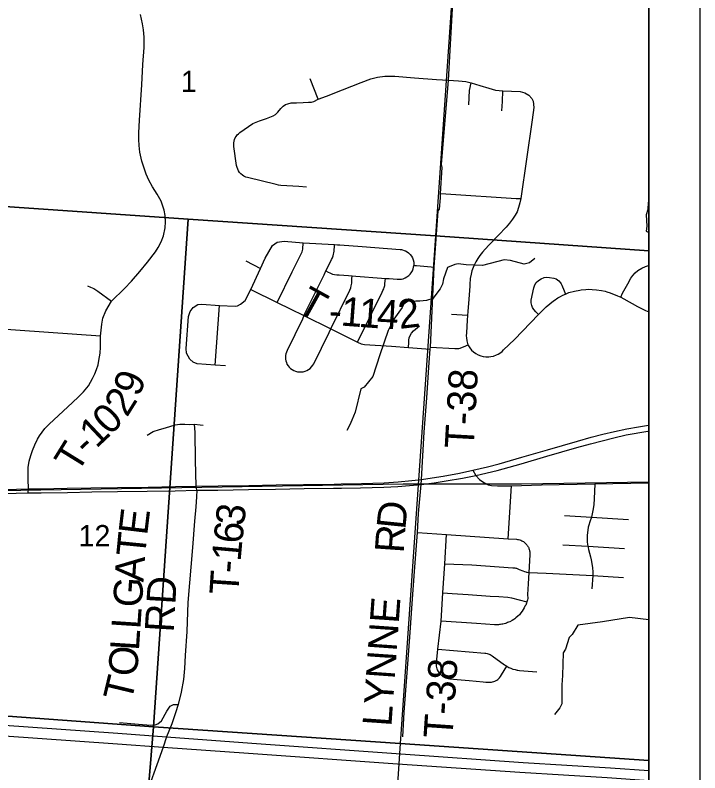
# Model space of a CAD drawing. Extents: x 0 to 34, y 0 to 22.
# Drawn here: x 7.657 to 9, y 18.88 to 20.367 of the extents above; entities that cross this region are included whole.
import ezdxf

# ---------------------------------------------------------------- set-up
doc = ezdxf.new("R2010")
doc.units = 0
for name, color, linetype in [('GM_X_Corporation', 7, 'Continuous'), ('GM_X_Interstate_Route', 7, 'Continuous'), ('GM_X_Minor_River', 7, 'Continuous'), ('GM_X_Rail_Line', 7, 'Continuous'), ('GM_X_Section_Text', 7, 'Continuous'), ('GM_X_Township_Road', 7, 'Continuous'), ('GM_X_Township_Road_Text', 7, 'Continuous'), ('GM_X_US_Route', 7, 'Continuous'), ('SH_Data', 7, 'Continuous')]:
    doc.layers.add(name, color=color, linetype=linetype)

msp = doc.modelspace()

# ---------------------------------------------------------------- linework, layer by layer
at = {"layer": 'GM_X_Corporation'}
for points in [[(6.0904, 18.0983), (6.5673, 18.064), (7.2487, 18.0119), (7.5344, 17.9901), (7.8447, 17.9665), (8.1742, 17.9461), (8.3494, 17.9349), (8.9, 17.9001), (8.9, 20.9), (4.3068, 20.9)], [(6.0906, 18.0978), (6.5646, 18.0583), (7.2489, 18.0114), (7.5346, 17.9896), (7.8449, 17.9659), (8.1744, 17.9455), (8.3496, 17.9344), (8.9, 17.8995), (8.9, 20.9), (4.3071, 20.9)], [(6.0904, 18.0983), (6.5673, 18.064), (7.2487, 18.0119), (7.5344, 17.9901), (7.8447, 17.9665), (8.1742, 17.9461), (8.3494, 17.9349), (8.9, 17.9001), (8.9, 20.4724), (8.5224, 20.4984), (8.4655, 20.5021), (7.8827, 20.5405), (6.676, 20.6183), (5.8237, 20.6711)]]:
    msp.add_lwpolyline(points, dxfattribs=at)
for points in [[(7.5154, 20.5644), (7.7109, 20.5519), (7.7144, 20.5517), (8.2347, 20.5164), (8.5204, 20.4957), (8.4813, 19.9336), (7.9967, 19.9667), (7.4756, 20.0027)], [(8.9, 19.9045), (8.9, 20.4692), (8.881, 20.4706), (8.6271, 20.4885), (8.5204, 20.4957), (8.4813, 19.9336)], [(7.4756, 20.0027), (7.9967, 19.9667), (7.9283, 18.9706), (7.41, 19.0084)], [(7.9967, 19.9667), (8.4813, 19.9336), (8.4119, 18.9377), (7.9283, 18.9706)], [(8.9, 18.9043), (8.9, 19.9045), (8.4813, 19.9336), (8.4119, 18.9377)], [(7.41, 19.0084), (7.9283, 18.9706), (7.8463, 17.9699), (7.3413, 18.0066)], [(7.9283, 18.9706), (8.4119, 18.9377), (8.3461, 17.9359), (7.8463, 17.9699)], [(8.9, 18.4545), (8.9, 18.9043), (8.4119, 18.9377), (8.3461, 17.9359), (8.8583, 17.9025)]]:
    msp.add_lwpolyline(points, close=True, dxfattribs=at)
at = {"layer": 'GM_X_Interstate_Route'}
for points in [[(6.2952, 19.0686), (6.6043, 19.0467), (6.911, 19.0252), (7.1726, 19.0063), (7.3941, 18.9908), (7.6264, 18.9743), (7.8582, 18.9579), (7.9538, 18.9505), (8.121, 18.9382), (8.4135, 18.9171), (8.6535, 18.9007), (8.825, 18.8902), (8.9, 18.885)], [(6.3995, 19.0399), (6.6039, 19.0257), (6.9106, 19.0042), (7.1722, 18.9854), (7.3938, 18.9698), (7.626, 18.9534), (7.8578, 18.937), (7.9472, 18.9307), (8.1146, 18.9188), (8.4071, 18.8978), (8.647, 18.8813), (8.8185, 18.8708), (8.9, 18.8652)]]:
    msp.add_lwpolyline(points, dxfattribs=at)
at = {"layer": 'GM_X_Minor_River'}
for points in [[(8.9, 20.0018), (8.8987, 19.9995), (8.8979, 19.9858), (8.8945, 19.9748), (8.8963, 19.9528), (8.8948, 19.943), (8.8997, 19.9407), (8.9, 19.9397)], [(8.6762, 19.8896), (8.6656, 19.8812), (8.6553, 19.8782), (8.6289, 19.8855), (8.616, 19.8867), (8.5735, 19.8757), (8.5417, 19.877), (8.5262, 19.8789), (8.5194, 19.8778), (8.505, 19.8717), (8.497, 19.8497), (8.4951, 19.8391), (8.4905, 19.8296), (8.4761, 19.8111), (8.464, 19.8069), (8.4511, 19.8058), (8.4431, 19.8054), (8.4265, 19.8051), (8.4193, 19.7998), (8.4159, 19.793), (8.3995, 19.7706), (8.3885, 19.7482), (8.3725, 19.7001), (8.3584, 19.658), (8.3413, 19.6371), (8.3352, 19.6337), (8.3238, 19.5878), (8.3173, 19.5723), (8.3135, 19.5632), (8.3078, 19.5518)], [(8.9, 19.1804), (8.8622, 19.185), (8.8088, 19.1767), (8.7607, 19.17), (8.7497, 19.1514), (8.7436, 19.1454), (8.7364, 19.123), (8.7322, 19.1154), (8.7306, 19.0714), (8.729, 19.0528), (8.7293, 19.0152), (8.7255, 19.0076), (8.7149, 18.9944)]]:
    msp.add_lwpolyline(points, dxfattribs=at)
at = {"layer": 'GM_X_Rail_Line'}
msp.add_lwpolyline([(3.8879, 19.3555), (4.0965, 19.3606), (5.5472, 19.3964), (6.4975, 19.4141), (6.7591, 19.4199), (8.4183, 19.4472), (8.6503, 19.4472), (8.9, 19.451)], dxfattribs=at)
at = {"layer": 'GM_X_Township_Road'}
for p, q in [((8.2513, 20.202), (8.2358, 20.2418)), ((8.1096, 19.8849), (8.1384, 19.8699)), ((8.0491, 19.6801), (8.0577, 19.7975)), ((8.5441, 19.7776), (8.5129, 19.7795)), ((8.6241, 19.3395), (8.6303, 19.4435)), ((8.7343, 19.3849), (8.7875, 19.3817)), ((8.7875, 19.3817), (8.8599, 19.3772)), ((8.7314, 19.3278), (8.78, 19.325)), ((8.78, 19.325), (8.8523, 19.3206))]:
    msp.add_line(p, q, dxfattribs=at)
for points in [[(8.4533, 19.4461), (8.4538, 19.4559), (8.4595, 19.5486), (8.4642, 19.6162), (8.4694, 19.6855), (8.4712, 19.7115), (8.4714, 19.7155), (8.4788, 19.8727), (8.4868, 19.9832), (8.4893, 19.9864), (8.491, 20.0087), (8.491, 20.017), (8.4943, 20.0681), (8.4934, 20.0737), (8.5073, 20.2393), (8.5154, 20.3909), (8.5226, 20.4978)], [(7.6828, 19.4293), (7.6829, 19.4373), (7.6826, 19.4561), (7.6824, 19.4794), (7.6847, 19.4919), (7.6881, 19.5027), (7.6911, 19.5126), (7.6955, 19.5236), (7.7006, 19.5348), (7.7047, 19.5417), (7.7098, 19.5489), (7.7154, 19.5558), (7.7238, 19.5645), (7.7698, 19.6071), (7.7815, 19.6181), (7.7909, 19.6278), (7.8009, 19.6398), (7.8086, 19.6538), (7.8134, 19.6633), (7.8167, 19.6717), (7.8198, 19.6809), (7.8213, 19.6893), (7.8236, 19.7036), (7.8244, 19.7154), (7.8241, 19.7371), (7.8269, 19.7608), (7.8293, 19.7721), (7.8348, 19.7867), (7.846, 19.8055), (7.8716, 19.8308), (7.8854, 19.8451), (7.9015, 19.8639), (7.9166, 19.8822), (7.9322, 19.9026), (7.9375, 19.911), (7.9434, 19.9218), (7.948, 19.9339), (7.9511, 19.9494), (7.9517, 19.9611), (7.951, 19.974), (7.9492, 19.9845), (7.9435, 20.0017), (7.9356, 20.0158), (7.9263, 20.0298), (7.919, 20.0434), (7.9141, 20.0549), (7.9098, 20.0668), (7.9056, 20.0807), (7.9019, 20.0978), (7.9002, 20.1114), (7.8993, 20.1227), (7.8994, 20.1362), (7.9009, 20.161), (7.9054, 20.23), (7.9077, 20.2698), (7.91, 20.3033), (7.9103, 20.3118), (7.91, 20.3237), (7.9089, 20.3382), (7.9071, 20.3498), (7.903, 20.3679)], [(8.1229, 20.1543), (8.1365, 20.1596), (8.15, 20.1642), (8.1533, 20.1655), (8.1632, 20.1692), (8.1678, 20.1719), (8.1724, 20.1766), (8.178, 20.1836), (8.1826, 20.1881), (8.1872, 20.1915), (8.1918, 20.1932), (8.1986, 20.1946), (8.2088, 20.1948), (8.2222, 20.1956), (8.2322, 20.196), (8.238, 20.1965), (8.2431, 20.1978), (8.2513, 20.202), (8.2674, 20.2077), (8.2993, 20.2207), (8.3356, 20.2349), (8.3548, 20.2418), (8.3678, 20.2453), (8.3823, 20.2472), (8.4019, 20.2472), (8.4404, 20.2437), (8.4833, 20.2405), (8.5073, 20.2393)], [(8.5073, 20.2393), (8.5269, 20.238), (8.5411, 20.2368), (8.5515, 20.2339), (8.5686, 20.2289), (8.5863, 20.2235), (8.5992, 20.2197), (8.6137, 20.2181), (8.6475, 20.2172), (8.657, 20.2143), (8.6649, 20.2096), (8.6705, 20.2036), (8.6734, 20.1979), (8.6743, 20.1859), (8.6712, 20.1616), (8.6486, 20.0072), (8.6468, 19.9984), (8.6445, 19.9896), (8.6414, 19.9813), (8.6377, 19.9742), (8.6352, 19.9702), (8.6327, 19.9663), (8.6269, 19.9586), (8.6203, 19.9512), (8.6052, 19.935), (8.5871, 19.9161), (8.5789, 19.9074), (8.5736, 19.9016), (8.5686, 19.8952), (8.5644, 19.8893), (8.5604, 19.8827), (8.5568, 19.8749), (8.5529, 19.8653), (8.5512, 19.8584), (8.5498, 19.8503), (8.5493, 19.8463), (8.5489, 19.8424), (8.5486, 19.8351), (8.5468, 19.8099), (8.5451, 19.7852), (8.5441, 19.7776), (8.5436, 19.7685), (8.5421, 19.7438), (8.5419, 19.7377), (8.5421, 19.7338), (8.5431, 19.7279), (8.545, 19.7201), (8.5462, 19.7178), (8.5486, 19.714), (8.5523, 19.7096), (8.5558, 19.7063), (8.5607, 19.7028), (8.5655, 19.7001), (8.5705, 19.6982), (8.5749, 19.6971), (8.5803, 19.6964), (8.5863, 19.6963), (8.5899, 19.6968), (8.5956, 19.698), (8.6014, 19.7002), (8.6046, 19.7019), (8.6098, 19.7052), (8.6121, 19.7072), (8.6152, 19.7102), (8.6363, 19.7304), (8.6835, 19.7793), (8.6908, 19.7865), (8.6989, 19.7943), (8.7056, 19.8003), (8.7131, 19.8061), (8.7143, 19.807), (8.7216, 19.812), (8.7264, 19.8146), (8.7313, 19.8173), (8.7363, 19.8194), (8.7429, 19.8224), (8.7543, 19.8254), (8.7647, 19.8275), (8.7673, 19.8277), (8.7764, 19.8287), (8.7818, 19.8289), (8.7886, 19.8287), (8.797, 19.8281), (8.8072, 19.8267), (8.8146, 19.825), (8.8179, 19.824), (8.8239, 19.8221), (8.8383, 19.8162), (8.8449, 19.8133), (8.8506, 19.8102), (8.8776, 19.7951), (8.8854, 19.7914), (8.8908, 19.7885), (8.8935, 19.7874), (8.9, 19.7848), (8.9, 19.7848)], [(8.5468, 20.191), (8.5484, 20.2191), (8.5515, 20.2339)], [(8.6118, 20.179), (8.6129, 20.1978), (8.6137, 20.2181)], [(8.2285, 20.0295), (8.2135, 20.0305), (8.1779, 20.0329), (8.1735, 20.0334), (8.169, 20.0343), (8.1128, 20.0482), (8.1092, 20.0493), (8.1058, 20.0509), (8.1027, 20.0529), (8.0998, 20.0554), (8.0973, 20.0581), (8.0952, 20.0612), (8.0935, 20.0646), (8.0922, 20.0681), (8.0914, 20.0718), (8.0861, 20.1093), (8.0858, 20.1127), (8.0859, 20.1161), (8.0865, 20.1195), (8.0875, 20.1229), (8.0888, 20.126), (8.0906, 20.129), (8.0926, 20.1318), (8.095, 20.1342), (8.0977, 20.1364), (8.1229, 20.1543)], [(8.491, 20.017), (8.5021, 20.016), (8.6397, 20.0073), (8.6486, 20.0072)], [(8.0696, 19.6785), (8.0491, 19.6801), (8.0138, 19.6829), (8.0061, 19.686), (7.9998, 19.6921), (7.9931, 19.7039), (7.9924, 19.713), (7.9973, 19.7758), (8.0001, 19.7851), (8.0061, 19.7931), (8.0156, 19.7989), (8.023, 19.7995), (8.0577, 19.7975), (8.0886, 19.7957), (8.0933, 19.7967), (8.0991, 19.7998), (8.1081, 19.8069), (8.1192, 19.8284), (8.1384, 19.8699), (8.1471, 19.8898), (8.1617, 19.9147), (8.1711, 19.9214), (8.185, 19.9233), (8.2219, 19.9203), (8.2836, 19.9166), (8.2893, 19.9162), (8.2941, 19.916), (8.3378, 19.9127), (8.4123, 19.9072), (8.4151, 19.9068), (8.4168, 19.9065), (8.4199, 19.9054), (8.4228, 19.9042), (8.4259, 19.9024), (8.4286, 19.9004), (8.4318, 19.8972), (8.4342, 19.8942), (8.4361, 19.8909), (8.4376, 19.8867), (8.4388, 19.8824), (8.4392, 19.8757), (8.444, 19.8754), (8.4727, 19.8731), (8.4788, 19.8727)], [(8.1711, 19.8029), (8.2001, 19.8632), (8.2197, 19.9027), (8.221, 19.9077), (8.2219, 19.9203)], [(8.2233, 19.7775), (8.2629, 19.8575), (8.2663, 19.8649), (8.2696, 19.8713), (8.2776, 19.8873), (8.2792, 19.8907), (8.2805, 19.8946), (8.2815, 19.8978), (8.2821, 19.9007), (8.2826, 19.9041), (8.2829, 19.9077), (8.2833, 19.9111), (8.2836, 19.9166)], [(8.2663, 19.8649), (8.271, 19.8625), (8.274, 19.861), (8.2767, 19.8599), (8.2797, 19.8588), (8.2836, 19.8579), (8.2879, 19.8574), (8.2926, 19.8572), (8.3107, 19.8558), (8.3181, 19.8552), (8.3252, 19.8547), (8.3756, 19.851), (8.3833, 19.8504), (8.3906, 19.8499), (8.4066, 19.8487), (8.4107, 19.8486), (8.4145, 19.8489), (8.4178, 19.8497), (8.4217, 19.8512), (8.4255, 19.8531), (8.429, 19.8558), (8.4316, 19.8584), (8.4339, 19.8615), (8.4362, 19.8654), (8.4377, 19.8691), (8.4392, 19.8757)], [(8.8449, 19.8133), (8.8482, 19.8211), (8.8588, 19.8399), (8.8648, 19.8509), (8.8685, 19.8562), (8.8734, 19.8615), (8.8786, 19.8657), (8.8864, 19.8704), (8.8934, 19.8735), (8.8993, 19.8754), (8.9, 19.8755)], [(8.2761, 19.7511), (8.3133, 19.8272), (8.3153, 19.8316), (8.3163, 19.8356), (8.3169, 19.8385), (8.3172, 19.8411), (8.3177, 19.8495), (8.3181, 19.8552)], [(8.3286, 19.7249), (8.3769, 19.8231), (8.3785, 19.8264), (8.38, 19.8298), (8.3809, 19.8325), (8.3819, 19.8361), (8.3824, 19.8394), (8.3829, 19.8455), (8.3833, 19.8504)], [(8.6835, 19.7793), (8.6782, 19.7848), (8.6744, 19.7893), (8.672, 19.793), (8.6702, 19.7975), (8.669, 19.8024), (8.6689, 19.8079), (8.6742, 19.8321), (8.6761, 19.838), (8.6792, 19.8426), (8.6834, 19.8463), (8.6886, 19.8496), (8.6946, 19.8519), (8.6999, 19.8526), (8.7054, 19.8522), (8.7137, 19.8509), (8.7184, 19.8492), (8.7231, 19.8459), (8.7268, 19.8416), (8.7282, 19.8394), (8.7296, 19.8372), (8.734, 19.8261), (8.7363, 19.8194)], [(7.7989, 19.8355), (7.8046, 19.8334), (7.8115, 19.8303), (7.8193, 19.8255), (7.846, 19.8055)], [(8.1192, 19.8284), (8.1711, 19.8029), (8.1963, 19.7907), (8.2233, 19.7775), (8.2761, 19.7511), (8.3286, 19.7249), (8.336, 19.7221), (8.3424, 19.7209), (8.3951, 19.7172)], [(7.8241, 19.7371), (7.3419, 19.7713), (7.0664, 19.792), (7.0468, 19.54), (6.9731, 19.5453), (6.9695, 19.4255)], [(8.2233, 19.7775), (8.2208, 19.7706), (8.1903, 19.7089), (8.189, 19.7056), (8.188, 19.7023), (8.1874, 19.6989), (8.1873, 19.6954), (8.1875, 19.6919), (8.1882, 19.6885), (8.1893, 19.6852), (8.1902, 19.6823), (8.1922, 19.6791), (8.1946, 19.6762), (8.1973, 19.6736), (8.2004, 19.6714), (8.2037, 19.6696), (8.2072, 19.6682), (8.2109, 19.6673), (8.2146, 19.6668), (8.2182, 19.6667), (8.2221, 19.6671), (8.2258, 19.6681), (8.2293, 19.6696), (8.2326, 19.6715), (8.2356, 19.6738), (8.2384, 19.6765), (8.2408, 19.6798), (8.2427, 19.683), (8.2732, 19.7444), (8.2761, 19.7511)], [(8.4286, 19.7148), (8.4291, 19.7248), (8.4294, 19.7291), (8.43, 19.7339), (8.4315, 19.738), (8.4346, 19.7428), (8.4383, 19.7474), (8.45, 19.7574)], [(8.3951, 19.7172), (8.4286, 19.7148), (8.4712, 19.7115)], [(8.4714, 19.7155), (8.5195, 19.7125), (8.5225, 19.7125), (8.5248, 19.7125), (8.5274, 19.7129), (8.5302, 19.7137), (8.5345, 19.7151), (8.5399, 19.7175), (8.545, 19.7201)], [(7.9159, 19.5425), (7.9279, 19.5496), (7.9402, 19.554), (7.9475, 19.5559), (7.9607, 19.5597), (7.9708, 19.5627), (7.9798, 19.5641), (7.9899, 19.5641), (7.9995, 19.5638), (8.0087, 19.5641), (8.0197, 19.5627), (8.0259, 19.5625)], [(8.0131, 19.4347), (8.0121, 19.4425), (8.0109, 19.4938), (8.0098, 19.5482), (8.0087, 19.5641)], [(8.5547, 19.4738), (8.5603, 19.4635), (8.568, 19.4557), (8.5765, 19.4496), (8.5845, 19.4455), (8.5911, 19.4439), (8.603, 19.4433), (8.6303, 19.4435), (8.6895, 19.4452), (8.7943, 19.4473), (8.9, 19.4492)], [(8.0131, 19.4347), (8.0127, 19.4218), (8.0113, 19.4018), (8.0088, 19.374), (8.0046, 19.3225), (7.9958, 19.2141), (7.9935, 19.1576), (7.9907, 19.1106)], [(8.4173, 18.951), (8.4203, 18.9994), (8.426, 19.0764), (8.432, 19.1557), (8.4359, 19.2126), (8.4402, 19.2753), (8.4461, 19.3518), (8.4483, 19.3893), (8.4533, 19.4461)], [(8.7943, 19.4473), (8.7928, 19.4179), (8.7921, 19.4069), (8.791, 19.3983), (8.7875, 19.3817), (8.7842, 19.3724), (8.7823, 19.3662), (8.7812, 19.3619), (8.7802, 19.3566), (8.7794, 19.352), (8.7789, 19.3459), (8.7787, 19.3411), (8.7789, 19.3378), (8.7791, 19.3327), (8.78, 19.325), (8.7807, 19.3225), (8.7815, 19.3181), (8.7854, 19.3037), (8.7868, 19.2981), (8.7891, 19.2872), (8.7895, 19.2821), (8.7899, 19.2747), (8.7898, 19.2673), (8.7882, 19.2415)], [(8.4461, 19.3518), (8.5032, 19.3475), (8.6241, 19.3395), (8.6402, 19.3385), (8.6421, 19.3383), (8.6441, 19.3379), (8.6467, 19.3373), (8.648, 19.3369), (8.6492, 19.3364), (8.651, 19.3356), (8.6524, 19.3348), (8.654, 19.3338), (8.6558, 19.3324), (8.6577, 19.3309), (8.6607, 19.3276), (8.6616, 19.3265), (8.6622, 19.3256), (8.6629, 19.3244), (8.6637, 19.323), (8.6644, 19.3214), (8.6649, 19.3202), (8.6654, 19.3185), (8.6659, 19.317), (8.6661, 19.3156), (8.6664, 19.314), (8.6666, 19.3121), (8.6666, 19.3103), (8.6665, 19.3082), (8.6644, 19.2734), (8.6634, 19.2509), (8.6621, 19.2302), (8.6623, 19.2223), (8.6618, 19.2193), (8.6609, 19.2155), (8.6603, 19.213), (8.6589, 19.2092), (8.657, 19.2072), (8.6554, 19.2039), (8.6535, 19.2004), (8.6518, 19.1976), (8.6491, 19.194), (8.646, 19.1904), (8.6433, 19.1876), (8.6393, 19.184), (8.6371, 19.1823), (8.635, 19.181), (8.6318, 19.179), (8.6274, 19.1766), (8.625, 19.1756), (8.623, 19.1748), (8.6209, 19.174), (8.6189, 19.1733), (8.6164, 19.1726), (8.6139, 19.1721), (8.6115, 19.1716), (8.609, 19.1712), (8.6073, 19.171), (8.6051, 19.1708), (8.6032, 19.1707), (8.5973, 19.1708), (8.5619, 19.1732), (8.4928, 19.1774)], [(8.4902, 19.0748), (8.4887, 19.0767), (8.4873, 19.0789), (8.4857, 19.0819), (8.4848, 19.0842), (8.4842, 19.0868), (8.4837, 19.0893), (8.4834, 19.0918), (8.4836, 19.0938), (8.4837, 19.096), (8.4858, 19.123), (8.4928, 19.1774), (8.4961, 19.2335), (8.4996, 19.2903), (8.5032, 19.3475)], [(8.4996, 19.2903), (8.5531, 19.2884), (8.6335, 19.2827), (8.6352, 19.2826), (8.6363, 19.2824), (8.6373, 19.2823), (8.6388, 19.2819), (8.6402, 19.2815), (8.6419, 19.2809), (8.6459, 19.2792), (8.6526, 19.2766), (8.6559, 19.2754), (8.6584, 19.2745), (8.6599, 19.2741), (8.6611, 19.2739), (8.6644, 19.2734), (8.6986, 19.2722), (8.7898, 19.2673), (8.8505, 19.2635)], [(8.4961, 19.2335), (8.5139, 19.2323), (8.5455, 19.2303), (8.589, 19.227), (8.6059, 19.226), (8.6235, 19.2248), (8.6308, 19.2233), (8.6609, 19.2155)], [(8.4858, 19.123), (8.578, 19.1152), (8.5804, 19.115), (8.5829, 19.1144), (8.585, 19.1137), (8.587, 19.113), (8.589, 19.112), (8.5909, 19.1109), (8.5924, 19.1098), (8.6171, 19.0921), (8.6193, 19.0906), (8.6213, 19.0893), (8.6252, 19.0871), (8.6293, 19.0852), (8.6332, 19.0838), (8.6375, 19.0826), (8.6417, 19.0815), (8.6433, 19.0813), (8.6463, 19.081), (8.6804, 19.0782)], [(7.9907, 19.1106), (7.9891, 19.0847), (7.9869, 19.0632), (7.9829, 19.0385), (7.9768, 19.0145), (7.9715, 18.9979), (7.9641, 18.9765), (7.9538, 18.9505), (7.9472, 18.9307), (7.9351, 18.8956), (7.9202, 18.8539), (7.912, 18.8331), (7.9053, 18.8095), (7.9015, 18.7947), (7.8978, 18.7791), (7.8971, 18.7669), (7.891, 18.705), (7.8908, 18.703)], [(8.4902, 19.0748), (8.4945, 19.0706), (8.4962, 19.0693), (8.4982, 19.068), (8.5008, 19.0668), (8.5037, 19.0657), (8.5065, 19.065), (8.5094, 19.0645), (8.5242, 19.0633), (8.5474, 19.0611), (8.575, 19.0586), (8.5804, 19.0581), (8.5841, 19.0579), (8.5867, 19.0578), (8.5893, 19.058), (8.5915, 19.0582), (8.5936, 19.0587), (8.5959, 19.0594), (8.5978, 19.0601), (8.5995, 19.0609), (8.6018, 19.0622), (8.6036, 19.0634), (8.6052, 19.0646), (8.607, 19.0667), (8.609, 19.0692), (8.6111, 19.0724), (8.6213, 19.0893)], [(7.8615, 18.9786), (7.8988, 18.9754), (7.9232, 18.9737), (7.9317, 18.974), (7.9372, 18.9762), (7.9439, 18.9819), (7.9543, 19.0011), (7.9612, 19.0111), (7.9678, 19.0141), (7.9768, 19.0145)]]:
    msp.add_lwpolyline(points, dxfattribs=at)
at = {"layer": 'GM_X_US_Route'}
for points in [[(8.2968, 19.4469), (8.3362, 19.4476), (8.381, 19.4492), (8.4081, 19.4512), (8.4353, 19.4537), (8.4538, 19.4559), (8.4748, 19.4587), (8.4964, 19.4623), (8.5286, 19.4682), (8.5547, 19.4738), (8.5836, 19.4805), (8.6061, 19.4867), (8.6507, 19.4994), (8.7013, 19.5141), (8.7599, 19.5311), (8.787, 19.5387), (8.8097, 19.5444), (8.8328, 19.5499), (8.857, 19.5552), (8.8794, 19.5594), (8.8996, 19.5626), (8.9, 19.5627)], [(8.5603, 19.4635), (8.6024, 19.4734), (8.6493, 19.4866), (8.7, 19.5013), (8.7587, 19.5184), (8.7855, 19.5259), (8.8084, 19.5318), (8.8312, 19.5373), (8.8556, 19.5431), (8.8982, 19.5505), (8.9, 19.5507)], [(8.2973, 19.4389), (8.3343, 19.4394), (8.3803, 19.4407), (8.4076, 19.4422), (8.4533, 19.4461), (8.479, 19.4494), (8.5022, 19.453), (8.5345, 19.4584), (8.5603, 19.4635)], [(7.5996, 19.4277), (7.6589, 19.4289), (7.6828, 19.4293), (7.7081, 19.4296), (7.7594, 19.4304), (7.8071, 19.4312), (7.8578, 19.4321), (7.9161, 19.433), (7.9707, 19.4338), (8.0131, 19.4347)], [(7.5997, 19.4357), (7.6595, 19.4368), (7.6829, 19.4373), (7.7065, 19.4376), (7.7593, 19.4385), (7.8053, 19.4392), (7.8576, 19.4401), (7.9182, 19.441), (7.9715, 19.4419), (8.0121, 19.4425), (8.055, 19.4432), (8.1155, 19.4441), (8.1689, 19.4451), (8.2228, 19.4459), (8.283, 19.4467), (8.2968, 19.4469)], [(8.0131, 19.4347), (8.0545, 19.4351), (8.1149, 19.4362), (8.1679, 19.4369), (8.2241, 19.4378), (8.2817, 19.4387), (8.2973, 19.4389)]]:
    msp.add_lwpolyline(points, dxfattribs=at)
at = {"layer": 'SH_Data'}
for p, q in [((9, 21), (9, 14)), ((8.9, 20.9), (8.9, 14.1))]:
    msp.add_line(p, q, dxfattribs=at)

# ---------------------------------------------------------------- texts
at = {"layer": 'GM_X_Section_Text'}
for s, height, p in [('1', 0.0419, (7.9819, 20.2159)), ('12', 0.04186, (7.7815, 19.3245))]:
    msp.add_text(s, height=height, rotation=0, dxfattribs=at).set_placement(p)
at = {"layer": 'GM_X_Township_Road_Text'}
for s, height, rotation, p in [('T', 0.0568, 330.9887, (8.2074, 19.7874)), ('1', 0.0568, 355.64, (8.2944, 19.758)), ('1', 0.0568, 355.8766, (8.3296, 19.7553)), ('4', 0.0568, 356.875, (8.3656, 19.7527)), ('2', 0.0568, 6.6516, (8.4111, 19.7511)), ('-', 0.0568, 357.1196, (8.2715, 19.7591)), ('9', 0.0568, 68.2795, (7.8998, 19.616)), ('T-38', 0.05682, 86.8206, (8.5562, 19.5153)), ('2', 0.0568, 58.0091, (7.8763, 19.5764)), ('0', 0.0568, 45.0771, (7.8429, 19.5407)), ('1', 0.0568, 43.3027, (7.816, 19.5154)), ('T', 0.0568, 58.2858, (7.7792, 19.4663)), ('-', 0.0568, 43.2777, (7.799, 19.4994)), ('3', 0.0568, 83.4546, (8.1058, 19.3631)), ('D', 0.0568, 84.231, (8.4222, 19.3564)), ('E', 0.0568, 83.2561, (7.9159, 19.3449)), ('6', 0.0568, 83.9834, (8.1022, 19.3284)), ('R', 0.0568, 86.0431, (8.419, 19.3103)), ('T', 0.0568, 84.4284, (7.9118, 19.3029)), ('1', 0.0568, 84.8932, (8.0991, 19.2938)), ('A', 0.0568, 86.2453, (7.9086, 19.2535)), ('-', 0.0568, 85.6947, (8.0974, 19.2707)), ('T', 0.0568, 86.1614, (8.0945, 19.2285)), ('G', 0.0568, 86.2467, (7.9053, 19.2036)), ('RD', 0.05682, 86.5467, (7.9678, 19.1549)), ('LYNNE', 0.05682, 85.9295, (8.3949, 18.9699)), ('L', 0.0568, 86.2475, (7.9025, 19.1612)), ('L', 0.0568, 86.2526, (7.8997, 19.1188)), ('O', 0.0568, 85.6534, (7.8959, 19.0683)), ('T-38', 0.05682, 86.091, (8.5145, 18.9466)), ('T', 0.0568, 76.5084, (7.8845, 19.0172))]:
    msp.add_text(s, height=height, rotation=rotation, dxfattribs=at).set_placement(p)

doc.saveas('drawing.dxf')
